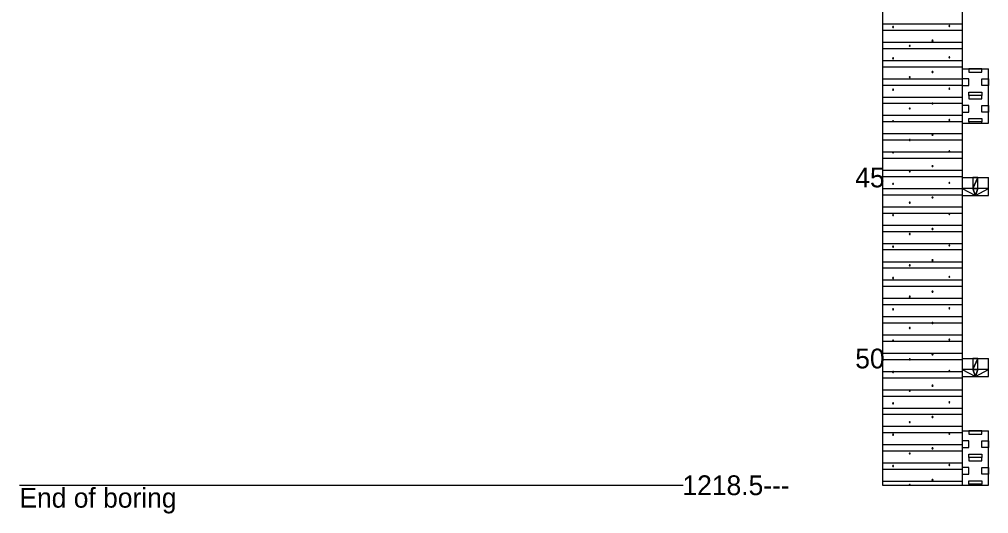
# Model space of a CAD drawing. Extents: x 2150161.5 to 2150203.1, y 143779.5 to 143868.5.
# Drawn here: x 2150186.76 to 2150192.84, y 143843.11 to 143846.21 of the extents above; entities that cross this region are included whole.
import ezdxf

# ---------------------------------------------------------------- set-up
doc = ezdxf.new("R2010")
doc.units = 0
doc.layers.add('Default', color=7, linetype='Continuous')

msp = doc.modelspace()

# ---------------------------------------------------------------- linework, layer by layer
at = {"layer": 'Default'}
for points in [[(2150192.1772, 143855.4435), (2150192.1772, 143843.2844)], [(2150192.6772, 143855.4435), (2150192.6772, 143843.2844)], [(2150192.1772, 143846.1805), (2150192.6772, 143846.1805)], [(2150192.2476, 143846.1606), (2150192.2459, 143846.1634), (2150192.2427, 143846.1634), (2150192.241, 143846.1606), (2150192.2427, 143846.1577), (2150192.2459, 143846.1577), (2150192.2476, 143846.1606)], [(2150192.6003, 143846.1671), (2150192.5987, 143846.17), (2150192.5954, 143846.17), (2150192.5938, 143846.1671), (2150192.5954, 143846.1643), (2150192.5987, 143846.1643), (2150192.6003, 143846.1671)], [(2150192.1772, 143846.1412), (2150192.6772, 143846.1412)], [(2150192.1772, 143846.0657), (2150192.6772, 143846.0657)], [(2150192.3522, 143846.0427), (2150192.3506, 143846.0456), (2150192.3473, 143846.0456), (2150192.3457, 143846.0427), (2150192.3473, 143846.0398), (2150192.3506, 143846.0398), (2150192.3522, 143846.0427)], [(2150192.4948, 143846.0746), (2150192.4932, 143846.0774), (2150192.4899, 143846.0774), (2150192.4883, 143846.0746), (2150192.4899, 143846.0717), (2150192.4932, 143846.0717), (2150192.4948, 143846.0746)], [(2150192.1772, 143846.0263), (2150192.6772, 143846.0263)], [(2150192.6003, 143845.9702), (2150192.5987, 143845.9731), (2150192.5954, 143845.9731), (2150192.5938, 143845.9702), (2150192.5954, 143845.9674), (2150192.5987, 143845.9674), (2150192.6003, 143845.9702)], [(2150192.1772, 143845.9509), (2150192.6772, 143845.9509)], [(2150192.1772, 143845.9115), (2150192.6772, 143845.9115)], [(2150192.2476, 143845.9637), (2150192.2459, 143845.9665), (2150192.2427, 143845.9665), (2150192.241, 143845.9637), (2150192.2427, 143845.9608), (2150192.2459, 143845.9608), (2150192.2476, 143845.9637)], [(2150192.3522, 143845.8458), (2150192.3506, 143845.8487), (2150192.3473, 143845.8487), (2150192.3457, 143845.8459), (2150192.3473, 143845.843), (2150192.3506, 143845.843), (2150192.3522, 143845.8458)], [(2150192.4948, 143845.8777), (2150192.4932, 143845.8805), (2150192.4899, 143845.8805), (2150192.4883, 143845.8777), (2150192.4899, 143845.8749), (2150192.4932, 143845.8749), (2150192.4948, 143845.8777)], [(2150192.6772, 143845.8981), (2150192.8438, 143845.8981)], [(2150192.8438, 143845.5572), (2150192.8438, 143845.8981)], [(2150192.1772, 143845.836), (2150192.6772, 143845.836)], [(2150192.1772, 143845.7967), (2150192.6772, 143845.7967)], [(2150192.2476, 143845.7669), (2150192.2459, 143845.7697), (2150192.2427, 143845.7697), (2150192.241, 143845.7669), (2150192.2427, 143845.764), (2150192.2459, 143845.764), (2150192.2476, 143845.7669)], [(2150192.6003, 143845.7734), (2150192.5987, 143845.7763), (2150192.5954, 143845.7763), (2150192.5938, 143845.7734), (2150192.5954, 143845.7706), (2150192.5987, 143845.7706), (2150192.6003, 143845.7734)], [(2150192.1772, 143845.7212), (2150192.6772, 143845.7212)], [(2150192.1772, 143845.6818), (2150192.6772, 143845.6818)], [(2150192.4948, 143845.6809), (2150192.4932, 143845.6837), (2150192.4899, 143845.6837), (2150192.4883, 143845.6809), (2150192.4899, 143845.678), (2150192.4932, 143845.678), (2150192.4948, 143845.6809)], [(2150192.1772, 143845.6064), (2150192.6772, 143845.6064)], [(2150192.3522, 143845.649), (2150192.3506, 143845.6519), (2150192.3473, 143845.6519), (2150192.3457, 143845.649), (2150192.3473, 143845.6461), (2150192.3506, 143845.6461), (2150192.3522, 143845.649)], [(2150192.1772, 143845.567), (2150192.6772, 143845.567)], [(2150192.2476, 143845.57), (2150192.2459, 143845.5728), (2150192.2427, 143845.5728), (2150192.241, 143845.57), (2150192.2427, 143845.5671), (2150192.2459, 143845.5671), (2150192.2476, 143845.57)], [(2150192.6003, 143845.5765), (2150192.5987, 143845.5794), (2150192.5954, 143845.5794), (2150192.5938, 143845.5765), (2150192.5954, 143845.5737), (2150192.5987, 143845.5737), (2150192.6003, 143845.5765)], [(2150192.6772, 143845.5572), (2150192.8438, 143845.5572)], [(2150192.1772, 143845.4915), (2150192.6772, 143845.4915)], [(2150192.4948, 143845.484), (2150192.4932, 143845.4868), (2150192.4899, 143845.4868), (2150192.4883, 143845.484), (2150192.4899, 143845.4812), (2150192.4932, 143845.4812), (2150192.4948, 143845.484)], [(2150192.1772, 143845.4522), (2150192.6772, 143845.4522)], [(2150192.3522, 143845.4521), (2150192.3506, 143845.455), (2150192.3473, 143845.455), (2150192.3457, 143845.4522), (2150192.3473, 143845.4493), (2150192.3506, 143845.4493), (2150192.3522, 143845.4521)], [(2150192.1772, 143845.3767), (2150192.6772, 143845.3767)], [(2150192.2476, 143845.3732), (2150192.2459, 143845.376), (2150192.2427, 143845.376), (2150192.241, 143845.3732), (2150192.2427, 143845.3703), (2150192.2459, 143845.3703), (2150192.2476, 143845.3732)], [(2150192.6003, 143845.3797), (2150192.5987, 143845.3826), (2150192.5954, 143845.3826), (2150192.5938, 143845.3797), (2150192.5954, 143845.3769), (2150192.5987, 143845.3769), (2150192.6003, 143845.3797)], [(2150192.1772, 143845.3374), (2150192.6772, 143845.3374)], [(2150192.1772, 143845.2619), (2150192.6772, 143845.2619)], [(2150192.3522, 143845.2553), (2150192.3506, 143845.2582), (2150192.3473, 143845.2582), (2150192.3457, 143845.2553), (2150192.3473, 143845.2524), (2150192.3506, 143845.2524), (2150192.3522, 143845.2553)], [(2150192.4948, 143845.2872), (2150192.4932, 143845.29), (2150192.4899, 143845.29), (2150192.4883, 143845.2872), (2150192.4899, 143845.2843), (2150192.4932, 143845.2843), (2150192.4948, 143845.2872)], [(2150192.1772, 143845.2225), (2150192.6772, 143845.2225)], [(2150192.2476, 143845.1763), (2150192.2459, 143845.1791), (2150192.2427, 143845.1791), (2150192.241, 143845.1763), (2150192.2427, 143845.1734), (2150192.2459, 143845.1734), (2150192.2476, 143845.1763)], [(2150192.6003, 143845.1828), (2150192.5987, 143845.1857), (2150192.5954, 143845.1857), (2150192.5938, 143845.1828), (2150192.5954, 143845.18), (2150192.5987, 143845.18), (2150192.6003, 143845.1828)], [(2150192.6772, 143845.2163), (2150192.8438, 143845.2163)], [(2150192.8438, 143845.1026), (2150192.8438, 143845.2163)], [(2150192.1772, 143845.1471), (2150192.6772, 143845.1471)], [(2150192.1772, 143845.1077), (2150192.6772, 143845.1077)], [(2150192.3522, 143845.0584), (2150192.3506, 143845.0613), (2150192.3473, 143845.0613), (2150192.3457, 143845.0585), (2150192.3473, 143845.0556), (2150192.3506, 143845.0556), (2150192.3522, 143845.0584)], [(2150192.4948, 143845.0903), (2150192.4932, 143845.0931), (2150192.4899, 143845.0931), (2150192.4883, 143845.0903), (2150192.4899, 143845.0875), (2150192.4932, 143845.0875), (2150192.4948, 143845.0903)], [(2150192.6772, 143845.1026), (2150192.8438, 143845.1026)], [(2150192.1772, 143845.0322), (2150192.6772, 143845.0322)], [(2150192.1772, 143844.9929), (2150192.6772, 143844.9929)], [(2150192.2476, 143844.9795), (2150192.2459, 143844.9823), (2150192.2427, 143844.9823), (2150192.241, 143844.9795), (2150192.2427, 143844.9766), (2150192.2459, 143844.9766), (2150192.2476, 143844.9795)], [(2150192.6003, 143844.986), (2150192.5987, 143844.9889), (2150192.5954, 143844.9889), (2150192.5938, 143844.986), (2150192.5954, 143844.9832), (2150192.5987, 143844.9832), (2150192.6003, 143844.986)], [(2150192.1772, 143844.9174), (2150192.6772, 143844.9174)], [(2150192.1772, 143844.878), (2150192.6772, 143844.878)], [(2150192.4948, 143844.8935), (2150192.4932, 143844.8963), (2150192.4899, 143844.8963), (2150192.4883, 143844.8935), (2150192.4899, 143844.8906), (2150192.4932, 143844.8906), (2150192.4948, 143844.8935)], [(2150192.3522, 143844.8616), (2150192.3506, 143844.8645), (2150192.3473, 143844.8645), (2150192.3457, 143844.8616), (2150192.3473, 143844.8587), (2150192.3506, 143844.8587), (2150192.3522, 143844.8616)], [(2150192.1772, 143844.8026), (2150192.6772, 143844.8026)], [(2150192.1772, 143844.7632), (2150192.6772, 143844.7632)], [(2150192.2476, 143844.7826), (2150192.2459, 143844.7854), (2150192.2427, 143844.7854), (2150192.241, 143844.7826), (2150192.2427, 143844.7797), (2150192.2459, 143844.7797), (2150192.2476, 143844.7826)], [(2150192.6003, 143844.7891), (2150192.5987, 143844.792), (2150192.5954, 143844.792), (2150192.5938, 143844.7891), (2150192.5954, 143844.7863), (2150192.5987, 143844.7863), (2150192.6003, 143844.7891)], [(2150192.4948, 143844.6966), (2150192.4932, 143844.6994), (2150192.4899, 143844.6994), (2150192.4883, 143844.6966), (2150192.4899, 143844.6938), (2150192.4932, 143844.6938), (2150192.4948, 143844.6966)], [(2150192.1772, 143844.6877), (2150192.6772, 143844.6877)], [(2150192.1772, 143844.6484), (2150192.6772, 143844.6484)], [(2150192.3522, 143844.6647), (2150192.3506, 143844.6676), (2150192.3473, 143844.6676), (2150192.3457, 143844.6648), (2150192.3473, 143844.6619), (2150192.3506, 143844.6619), (2150192.3522, 143844.6647)], [(2150192.1772, 143844.5729), (2150192.6772, 143844.5729)], [(2150192.2476, 143844.5858), (2150192.2459, 143844.5886), (2150192.2427, 143844.5886), (2150192.241, 143844.5858), (2150192.2427, 143844.5829), (2150192.2459, 143844.5829), (2150192.2476, 143844.5858)], [(2150192.6003, 143844.5923), (2150192.5987, 143844.5952), (2150192.5954, 143844.5952), (2150192.5938, 143844.5923), (2150192.5954, 143844.5895), (2150192.5987, 143844.5895), (2150192.6003, 143844.5923)], [(2150192.1772, 143844.5335), (2150192.6772, 143844.5335)], [(2150192.1772, 143844.4581), (2150192.6772, 143844.4581)], [(2150192.3522, 143844.4679), (2150192.3506, 143844.4708), (2150192.3473, 143844.4708), (2150192.3457, 143844.4679), (2150192.3473, 143844.465), (2150192.3506, 143844.465), (2150192.3522, 143844.4679)], [(2150192.4948, 143844.4998), (2150192.4932, 143844.5026), (2150192.4899, 143844.5026), (2150192.4883, 143844.4998), (2150192.4899, 143844.4969), (2150192.4932, 143844.4969), (2150192.4948, 143844.4998)], [(2150192.1772, 143844.4187), (2150192.6772, 143844.4187)], [(2150192.2476, 143844.3889), (2150192.2459, 143844.3917), (2150192.2427, 143844.3917), (2150192.241, 143844.3889), (2150192.2427, 143844.386), (2150192.2459, 143844.386), (2150192.2476, 143844.3889)], [(2150192.6003, 143844.3954), (2150192.5987, 143844.3983), (2150192.5954, 143844.3983), (2150192.5938, 143844.3954), (2150192.5954, 143844.3926), (2150192.5987, 143844.3926), (2150192.6003, 143844.3954)], [(2150192.1772, 143844.3433), (2150192.6772, 143844.3433)], [(2150192.1772, 143844.3039), (2150192.6772, 143844.3039)], [(2150192.3522, 143844.271), (2150192.3506, 143844.2739), (2150192.3473, 143844.2739), (2150192.3457, 143844.2711), (2150192.3473, 143844.2682), (2150192.3506, 143844.2682), (2150192.3522, 143844.271)], [(2150192.4948, 143844.3029), (2150192.4932, 143844.3057), (2150192.4899, 143844.3057), (2150192.4883, 143844.3029), (2150192.4899, 143844.3001), (2150192.4932, 143844.3001), (2150192.4948, 143844.3029)], [(2150192.1772, 143844.2284), (2150192.6772, 143844.2284)], [(2150192.1772, 143844.1891), (2150192.6772, 143844.1891)], [(2150192.2476, 143844.1921), (2150192.2459, 143844.1949), (2150192.2427, 143844.1949), (2150192.241, 143844.1921), (2150192.2427, 143844.1892), (2150192.2459, 143844.1892), (2150192.2476, 143844.1921)], [(2150192.6003, 143844.1986), (2150192.5987, 143844.2015), (2150192.5954, 143844.2015), (2150192.5938, 143844.1986), (2150192.5954, 143844.1958), (2150192.5987, 143844.1958), (2150192.6003, 143844.1986)], [(2150192.1772, 143844.1136), (2150192.6772, 143844.1136)], [(2150192.4948, 143844.1061), (2150192.4932, 143844.1089), (2150192.4899, 143844.1089), (2150192.4883, 143844.1061), (2150192.4899, 143844.1032), (2150192.4932, 143844.1032), (2150192.4948, 143844.1061)], [(2150192.1772, 143844.0742), (2150192.6772, 143844.0742)], [(2150192.3522, 143844.0742), (2150192.3506, 143844.0771), (2150192.3473, 143844.0771), (2150192.3457, 143844.0742), (2150192.3473, 143844.0713), (2150192.3506, 143844.0713), (2150192.3522, 143844.0742)], [(2150192.6772, 143844.0799), (2150192.8438, 143844.0799)], [(2150192.8438, 143843.9663), (2150192.8438, 143844.0799)], [(2150192.1772, 143843.9988), (2150192.6772, 143843.9988)], [(2150192.2476, 143843.9952), (2150192.2459, 143843.998), (2150192.2427, 143843.998), (2150192.241, 143843.9952), (2150192.2427, 143843.9923), (2150192.2459, 143843.9923), (2150192.2476, 143843.9952)], [(2150192.6003, 143844.0017), (2150192.5987, 143844.0046), (2150192.5954, 143844.0046), (2150192.5938, 143844.0017), (2150192.5954, 143843.9989), (2150192.5987, 143843.9989), (2150192.6003, 143844.0017)], [(2150192.6772, 143843.9663), (2150192.8438, 143843.9663)], [(2150192.1772, 143843.9594), (2150192.6772, 143843.9594)], [(2150192.4948, 143843.9092), (2150192.4932, 143843.912), (2150192.4899, 143843.912), (2150192.4883, 143843.9092), (2150192.4899, 143843.9064), (2150192.4932, 143843.9064), (2150192.4948, 143843.9092)], [(2150192.1772, 143843.8839), (2150192.6772, 143843.8839)], [(2150192.1772, 143843.8446), (2150192.6772, 143843.8446)], [(2150192.3522, 143843.8773), (2150192.3506, 143843.8802), (2150192.3473, 143843.8802), (2150192.3457, 143843.8774), (2150192.3473, 143843.8745), (2150192.3506, 143843.8745), (2150192.3522, 143843.8773)], [(2150192.2476, 143843.7984), (2150192.2459, 143843.8012), (2150192.2427, 143843.8012), (2150192.241, 143843.7984), (2150192.2427, 143843.7955), (2150192.2459, 143843.7955), (2150192.2476, 143843.7984)], [(2150192.6003, 143843.8049), (2150192.5987, 143843.8078), (2150192.5954, 143843.8078), (2150192.5938, 143843.8049), (2150192.5954, 143843.8021), (2150192.5987, 143843.8021), (2150192.6003, 143843.8049)], [(2150192.1772, 143843.7691), (2150192.6772, 143843.7691)], [(2150192.1772, 143843.7297), (2150192.6772, 143843.7297)], [(2150192.3522, 143843.6805), (2150192.3506, 143843.6834), (2150192.3473, 143843.6834), (2150192.3457, 143843.6805), (2150192.3473, 143843.6776), (2150192.3506, 143843.6776), (2150192.3522, 143843.6805)], [(2150192.4948, 143843.7124), (2150192.4932, 143843.7152), (2150192.4899, 143843.7152), (2150192.4883, 143843.7124), (2150192.4899, 143843.7095), (2150192.4932, 143843.7095), (2150192.4948, 143843.7124)], [(2150192.1772, 143843.6543), (2150192.6772, 143843.6543)], [(2150192.1772, 143843.6149), (2150192.6772, 143843.6149)], [(2150192.2476, 143843.6015), (2150192.2459, 143843.6043), (2150192.2427, 143843.6043), (2150192.241, 143843.6015), (2150192.2427, 143843.5986), (2150192.2459, 143843.5986), (2150192.2476, 143843.6015)], [(2150192.6003, 143843.608), (2150192.5987, 143843.6109), (2150192.5954, 143843.6109), (2150192.5938, 143843.608), (2150192.5954, 143843.6052), (2150192.5987, 143843.6052), (2150192.6003, 143843.608)], [(2150192.6772, 143843.6254), (2150192.8438, 143843.6254)], [(2150192.8438, 143843.2844), (2150192.8438, 143843.6254)], [(2150192.1772, 143843.5395), (2150192.6772, 143843.5395)], [(2150192.1772, 143843.5001), (2150192.6772, 143843.5001)], [(2150192.3522, 143843.4836), (2150192.3506, 143843.4865), (2150192.3473, 143843.4865), (2150192.3457, 143843.4837), (2150192.3473, 143843.4808), (2150192.3506, 143843.4808), (2150192.3522, 143843.4836)], [(2150192.4948, 143843.5155), (2150192.4932, 143843.5183), (2150192.4899, 143843.5183), (2150192.4883, 143843.5155), (2150192.4899, 143843.5127), (2150192.4932, 143843.5127), (2150192.4948, 143843.5155)], [(2150192.1772, 143843.4246), (2150192.6772, 143843.4246)], [(2150192.6003, 143843.4112), (2150192.5987, 143843.4141), (2150192.5954, 143843.4141), (2150192.5938, 143843.4112), (2150192.5954, 143843.4084), (2150192.5987, 143843.4084), (2150192.6003, 143843.4112)], [(2150192.1772, 143843.3853), (2150192.6772, 143843.3853)], [(2150192.2476, 143843.4047), (2150192.2459, 143843.4075), (2150192.2427, 143843.4075), (2150192.241, 143843.4047), (2150192.2427, 143843.4018), (2150192.2459, 143843.4018), (2150192.2476, 143843.4047)], [(2150192.1772, 143843.3098), (2150192.6772, 143843.3098)], [(2150192.4948, 143843.3187), (2150192.4932, 143843.3215), (2150192.4899, 143843.3215), (2150192.4883, 143843.3187), (2150192.4899, 143843.3158), (2150192.4932, 143843.3158), (2150192.4948, 143843.3187)], [(2150186.7605, 143843.2844), (2150190.9272, 143843.2844)], [(2150192.1772, 143843.2844), (2150192.6772, 143843.2844)], [(2150192.3522, 143843.2868), (2150192.3506, 143843.2897), (2150192.3473, 143843.2897), (2150192.3457, 143843.2868), (2150192.347, 143843.2844), (2150192.3509, 143843.2844), (2150192.3522, 143843.2868)], [(2150192.6772, 143843.2844), (2150192.8438, 143843.2844)]]:
    msp.add_lwpolyline(points, dxfattribs=at)
for points in [[(2150192.7188, 143845.8981), (2150192.7188, 143845.8772), (2150192.8022, 143845.8772), (2150192.8022, 143845.8981)], [(2150192.6772, 143845.7939), (2150192.7188, 143845.7939), (2150192.7188, 143845.8356), (2150192.6772, 143845.8356)], [(2150192.8438, 143845.7939), (2150192.8022, 143845.7939), (2150192.8022, 143845.8356), (2150192.8438, 143845.8356)], [(2150192.7188, 143845.7314), (2150192.7188, 143845.7522), (2150192.8022, 143845.7522), (2150192.8022, 143845.7314)], [(2150192.7188, 143845.7314), (2150192.7188, 143845.7106), (2150192.8022, 143845.7106), (2150192.8022, 143845.7314)], [(2150192.6772, 143845.6272), (2150192.7188, 143845.6272), (2150192.7188, 143845.6689), (2150192.6772, 143845.6689)], [(2150192.8438, 143845.6272), (2150192.8022, 143845.6272), (2150192.8022, 143845.6689), (2150192.8438, 143845.6689)], [(2150192.7188, 143845.5647), (2150192.7188, 143845.5856), (2150192.8022, 143845.5856), (2150192.8022, 143845.5647)], [(2150192.8022, 143845.5647), (2150192.7188, 143845.5647), (2150192.7188, 143845.5572), (2150192.8022, 143845.5572)], [(2150192.7438, 143845.1481), (2150192.7772, 143845.1481), (2150192.7772, 143845.2163), (2150192.7438, 143845.1481)], [(2150192.7438, 143845.1481), (2150192.7772, 143845.2163), (2150192.7438, 143845.2163), (2150192.7438, 143845.1481)], [(2150192.7438, 143845.1481), (2150192.6772, 143845.1481), (2150192.7605, 143845.1026), (2150192.7438, 143845.1481)], [(2150192.7438, 143845.1481), (2150192.7605, 143845.1026), (2150192.7772, 143845.1481), (2150192.7438, 143845.1481)], [(2150192.7605, 143845.1026), (2150192.8438, 143845.1481), (2150192.7772, 143845.1481), (2150192.7605, 143845.1026)], [(2150192.7438, 143844.0117), (2150192.7772, 143844.0117), (2150192.7772, 143844.0799), (2150192.7438, 143844.0117)], [(2150192.7438, 143844.0117), (2150192.7772, 143844.0799), (2150192.7438, 143844.0799), (2150192.7438, 143844.0117)], [(2150192.7438, 143844.0117), (2150192.6772, 143844.0117), (2150192.7605, 143843.9663), (2150192.7438, 143844.0117)], [(2150192.7438, 143844.0117), (2150192.7605, 143843.9663), (2150192.7772, 143844.0117), (2150192.7438, 143844.0117)], [(2150192.7605, 143843.9663), (2150192.8438, 143844.0117), (2150192.7772, 143844.0117), (2150192.7605, 143843.9663)], [(2150192.7188, 143843.6254), (2150192.7188, 143843.6045), (2150192.8022, 143843.6045), (2150192.8022, 143843.6254)], [(2150192.6772, 143843.5212), (2150192.7188, 143843.5212), (2150192.7188, 143843.5629), (2150192.6772, 143843.5629)], [(2150192.8438, 143843.5212), (2150192.8022, 143843.5212), (2150192.8022, 143843.5629), (2150192.8438, 143843.5629)], [(2150192.7188, 143843.4587), (2150192.7188, 143843.4795), (2150192.8022, 143843.4795), (2150192.8022, 143843.4587)], [(2150192.7188, 143843.4587), (2150192.7188, 143843.4379), (2150192.8022, 143843.4379), (2150192.8022, 143843.4587)], [(2150192.6772, 143843.3545), (2150192.7188, 143843.3545), (2150192.7188, 143843.3962), (2150192.6772, 143843.3962)], [(2150192.8438, 143843.3545), (2150192.8022, 143843.3545), (2150192.8022, 143843.3962), (2150192.8438, 143843.3962)], [(2150192.7188, 143843.292), (2150192.7188, 143843.3129), (2150192.8022, 143843.3129), (2150192.8022, 143843.292)], [(2150192.8022, 143843.292), (2150192.7188, 143843.292), (2150192.7188, 143843.2844), (2150192.8022, 143843.2844)]]:
    msp.add_lwpolyline(points, close=True, dxfattribs=at)

# ---------------------------------------------------------------- texts
for s, p in [('45', (2150192.0068, 143845.1543)), ('50', (2150192.0068, 143844.0179)), ('1218.5---', (2150190.9223, 143843.2224)), ('End of boring', (2150186.7605, 143843.1438))]:
    msp.add_text(s, height=0.124, dxfattribs=at).set_placement(p)

doc.saveas('drawing.dxf')
